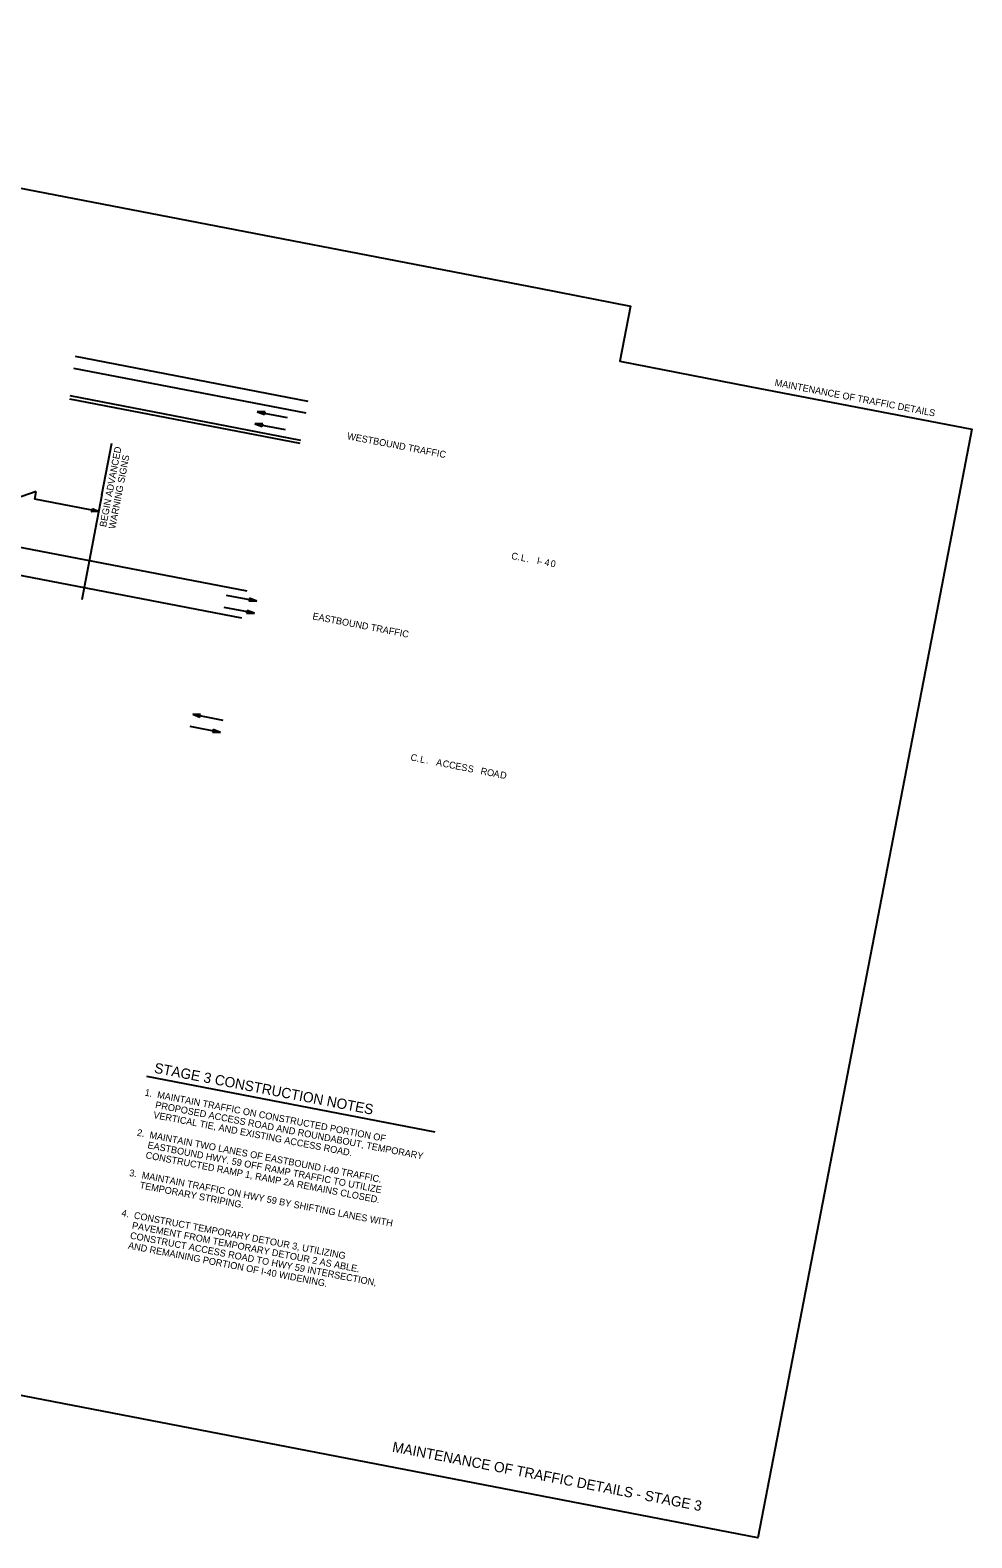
# Model space of a CAD drawing. Extents: x 605560 to 609391, y 416008 to 420725.
# Drawn here: x 606487 to 607315, y 419400 to 420725 of the extents above; entities that cross this region are included whole.
import ezdxf

# ---------------------------------------------------------------- set-up
doc = ezdxf.new("R2010")
doc.units = 0
for name, color, linetype in [('G-ANNO-TEXT', 7, 'Continuous'), ('G-No Plot-Border-1', 7, 'Continuous'), ('Level 62', 7, 'Continuous'), ('R_Draft', 7, 'Continuous'), ('S_EDGE_PAVEMENT', 7, 'Continuous'), ('S_SHOULDER', 7, 'Continuous')]:
    doc.layers.add(name, color=color, linetype=linetype)

msp = doc.modelspace()

# ---------------------------------------------------------------- linework, layer by layer
at = {"layer": 'G-No Plot-Border-1'}
msp.add_lwpolyline([(605560.5, 419701.9), (605758, 420725.3), (606934.3, 420498.3), (606934.3, 420498.3), (606934.3, 420498.3), (607014.8, 420482.7), (607005.4, 420434.1), (607119.6, 420412), (607315.1, 420374.3), (607315.1, 420374.3), (607284.2, 420214.2), (607284.2, 420214.2), (607126.9, 419399.5)], close=True, dxfattribs=at)
at = {"layer": 'Level 62'}
for p, q in [((606693.4, 420389.7), (606686.6, 420389.8)), ((606686.6, 420389.8), (606693, 420387.4)), ((606686.6, 420389.8), (606713, 420384.7)), ((606693.3, 420389.1), (606688.3, 420389.7)), ((606688.3, 420389.3), (606693.1, 420388)), ((606693, 420387.4), (606693.4, 420389.7)), ((606691.4, 420379), (606684.5, 420379.1)), ((606684.5, 420379.1), (606690.9, 420376.7)), ((606684.5, 420379.1), (606711, 420374)), ((606686.2, 420378.6), (606691, 420377.3)), ((606691.2, 420378.4), (606686.3, 420378.9)), ((606690.9, 420376.7), (606691.4, 420379)), ((606686.1, 420223.2), (606659.6, 420228.3)), ((606679.7, 420225.7), (606679.2, 420223.4)), ((606686.1, 420223.2), (606679.7, 420225.7)), ((606684, 420212.5), (606657.5, 420217.6)), ((606677.6, 420215), (606677.1, 420212.6)), ((606677.1, 420212.6), (606684, 420212.5)), ((606677.2, 420213.2), (606682.2, 420212.7)), ((606682.3, 420213), (606677.5, 420214.4)), ((606684, 420212.5), (606677.6, 420215)), ((606679.2, 420223.4), (606686.1, 420223.2)), ((606679.3, 420223.9), (606684.3, 420223.4)), ((606684.3, 420223.7), (606679.5, 420225.1)), ((606636.6, 420123.5), (606629.8, 420123.7)), ((606629.8, 420123.7), (606636.2, 420121.2)), ((606629.8, 420123.7), (606656.2, 420118.5)), ((606636.5, 420122.9), (606631.5, 420123.5)), ((606631.5, 420123.2), (606636.3, 420121.8)), ((606636.2, 420121.2), (606636.6, 420123.5)), ((606654.1, 420107.8), (606627.7, 420112.9)), ((606647.8, 420110.3), (606647.3, 420108)), ((606647.3, 420108), (606654.1, 420107.8)), ((606647.4, 420108.5), (606652.4, 420108)), ((606652.4, 420108.3), (606647.6, 420109.7)), ((606654.1, 420107.8), (606647.8, 420110.3))]:
    msp.add_line(p, q, dxfattribs=at)
at = {"layer": 'R_Draft'}
for p, q in [((606550, 420316.7), (606558.7, 420362)), ((606492.2, 420319.7), (606466, 420310.5)), ((606490.9, 420313), (606492.2, 420319.7)), ((606547.2, 420302.1), (606490.9, 420313)), ((606550, 420316.7), (606544.4, 420287.6)), ((606544.4, 420287.6), (606532.2, 420224.5))]:
    msp.add_line(p, q, dxfattribs=at)
msp.add_lwpolyline([(606541.6, 420304.7), (606547.2, 420302.1), (606541, 420301.8)], close=True, dxfattribs=at)
msp.add_lwpolyline([(606843.1, 419756.2), (606589.5, 419805.1)], dxfattribs=at)
at = {"layer": 'S_EDGE_PAVEMENT'}
for p, q in [((606729.5, 420388.4), (606525.1, 420427.9)), ((606677.7, 420232), (605699.3, 420420.8)), ((606724.9, 420364.5), (606521.9, 420403.7)), ((606673.1, 420208.2), (605694.6, 420396.5))]:
    msp.add_line(p, q, dxfattribs=at)
at = {"layer": 'S_SHOULDER'}
for p, q in [((606731.4, 420398.7), (606526.7, 420438.2)), ((606724.4, 420361.8), (606521.8, 420400.9))]:
    msp.add_line(p, q, dxfattribs=at)

# ---------------------------------------------------------------- texts
at = {"layer": 'G-ANNO-TEXT'}
for s, height, p in [('MAINTENANCE OF TRAFFIC DETAILS', 6, (607141.3, 420412.7)), ('MAINTENANCE OF TRAFFIC DETAILS - STAGE 3', 9, (606804.8, 419475.4))]:
    msp.add_text(s, height=height, rotation=349.0745, dxfattribs=at).set_placement(p)
at = {"layer": 'R_Draft'}
for s, height, rotation, p in [('WESTBOUND TRAFFIC', 6, 349.0745, (606765.3, 420365.7)), ('BEGIN ADVANCED', 6, 79.0745, (606553.6, 420288)), ('WARNING SIGNS', 6, 79.0745, (606561.7, 420286.4)), ('C', 6, 349.0744, (606909.6, 420260.3)), ('.', 6, 349.0744, (606915.1, 420259.2)), ('L', 6, 349.0744, (606918, 420258.7)), ('.', 6, 349.0744, (606923.3, 420257.7)), ('I', 6, 349.0744, (606932.1, 420256)), ('-', 6, 349.0744, (606934, 420255.6)), ('4', 6, 349.0744, (606938.8, 420254.7)), ('0', 6, 349.0744, (606944.1, 420253.6)), ('EASTBOUND TRAFFIC', 6, 349.0745, (606734.8, 420207.3)), ('C', 6, 348.9214, (606821, 420083.2)), ('.', 6, 348.9214, (606826.5, 420082.1)), ('L', 6, 348.9214, (606829.4, 420081.5)), ('.', 6, 348.9214, (606834.7, 420080.5)), ('A', 6, 348.9214, (606843.5, 420078.8)), ('C', 6, 348.9214, (606849.2, 420077.7)), ('C', 6, 348.9214, (606854.8, 420076.6)), ('E', 6, 348.9214, (606860.3, 420075.5)), ('S', 6, 348.9214, (606865.6, 420074.4)), ('S', 6, 348.9214, (606871.2, 420073.3)), ('R', 6, 348.9214, (606882.6, 420071.1)), ('O', 6, 348.9214, (606888.2, 420070)), ('A', 6, 348.9214, (606893.9, 420068.9)), ('D', 6, 348.9214, (606899.7, 420067.8)), ('STAGE 3 CONSTRUCTION NOTES', 9, 349.0919, (606595.4, 419808.6)), ('1. ', 6, 349.0745, (606587.2, 419788.5)), ('MAINTAIN TRAFFIC ON CONSTRUCTED PORTION OF ', 6, 349.0745, (606598.2, 419786.4)), ('PROPOSED ACCESS ROAD AND ROUNDABOUT, TEMPORARY ', 6, 349.0745, (606596.5, 419777.6)), ('VERTICAL TIE, AND EXISTING ACCESS ROAD.', 6, 349.0745, (606594.8, 419768.7)), ('2. ', 6, 349.0745, (606580.4, 419753.2)), ('MAINTAIN TWO LANES OF EASTBOUND I-40 TRAFFIC. ', 6, 349.0745, (606591.4, 419751.1)), ('CONSTRUCTED RAMP 1, RAMP 2A REMAINS CLOSED.', 6, 349.0745, (606588, 419733.4)), ('EASTBOUND HWY. 59 OFF RAMP TRAFFIC TO UTILIZE ', 6, 349.0745, (606589.7, 419742.2)), ('3.', 6, 349.0745, (606573.6, 419717.8)), ('TEMPORARY STRIPING.', 6, 349.0745, (606582.8, 419706.9)), ('MAINTAIN TRAFFIC ON HWY 59 BY SHIFTING LANES WITH ', 6, 349.0745, (606584.6, 419715.7)), ('4.', 6, 349.0745, (606566.8, 419682.5)), ('CONSTRUCT TEMPORARY DETOUR 3, UTILIZING ', 6, 349.0745, (606577.7, 419680.4)), ('PAVEMENT FROM TEMPORARY DETOUR 2 AS ABLE.', 6, 349.0745, (606576, 419671.5)), ('AND REMAINING PORTION OF I-40 WIDENING.', 6, 349.0745, (606572.6, 419653.9)), ('CONSTRUCT ACCESS ROAD TO HWY 59 INTERSECTION, ', 6, 349.0745, (606574.3, 419662.7))]:
    msp.add_text(s, height=height, rotation=rotation, dxfattribs=at).set_placement(p)

doc.saveas('drawing.dxf')
